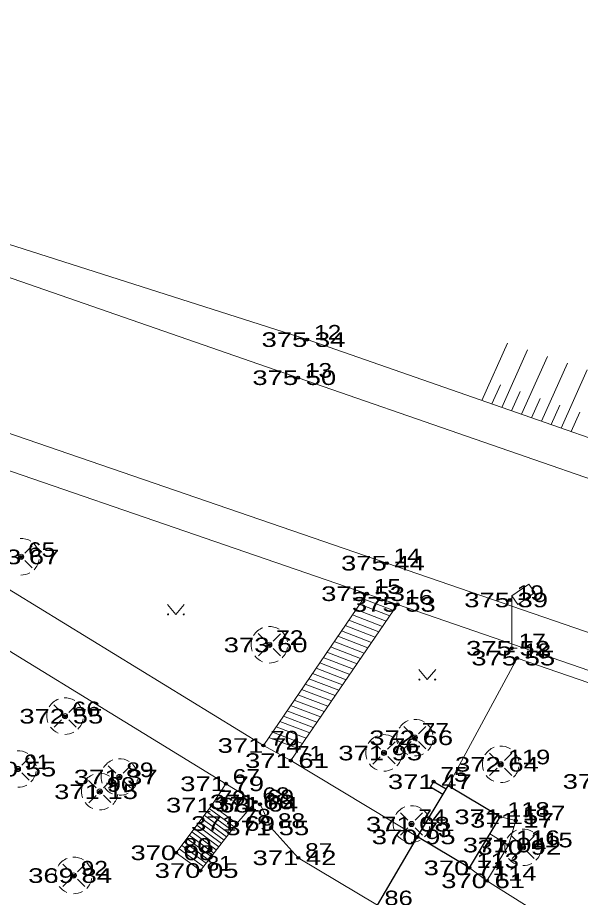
# Model space of a CAD drawing. Extents: x -789669 to -789458, y -977587 to -977420.
# Drawn here: x -789622.43 to -789595.52, y -977462.39 to -977420.32 of the extents above; entities that cross this region are included whole.
import ezdxf
from ezdxf.enums import TextEntityAlignment as Align

# ---------------------------------------------------------------- set-up
doc = ezdxf.new("R2010")
doc.units = 0
doc.header["$LTSCALE"] = 0.28
doc.header["$PDMODE"] = 32
doc.header["$PDSIZE"] = 0.14
for name, color, linetype, lineweight in [('1', 7, 'Continuous', 13), ('2', 7, 'Continuous', 13), ('3', 7, 'Continuous', 13), ('33', 7, 'Continuous', 13), ('4', 7, 'Continuous', 13), ('9', 7, 'Continuous', 25)]:
    doc.layers.add(name, color=color, linetype=linetype, lineweight=lineweight)
for name, color, linetype in [('57', 7, 'Continuous'), ('58', 7, 'Continuous'), ('59', 7, 'Continuous')]:
    doc.layers.add(name, color=color, linetype=linetype)

msp = doc.modelspace()

# ---------------------------------------------------------------- linework, layer by layer
at = {"layer": '1'}
for p, q in [((-789605.73, -977447.87), (-789610.68, -977455.13)), ((-789605.73, -977447.87), (-789604.26, -977448.38)), ((-789609.37, -977455.85), (-789604.26, -977448.38)), ((-789606.076, -977448.377), (-789604.634, -977448.927)), ((-789605.902, -977448.123), (-789604.46, -977448.672)), ((-789606.424, -977448.887), (-789604.983, -977449.436)), ((-789606.25, -977448.633), (-789604.809, -977449.182)), ((-789606.597, -977449.142), (-789605.157, -977449.691)), ((-789606.945, -977449.652), (-789605.505, -977450.2)), ((-789606.771, -977449.397), (-789605.331, -977449.946)), ((-789607.293, -977450.162), (-789605.854, -977450.71)), ((-789607.118, -977449.906), (-789605.679, -977450.455)), ((-789607.466, -977450.416), (-789606.028, -977450.964)), ((-789607.814, -977450.926), (-789606.376, -977451.474)), ((-789607.64, -977450.671), (-789606.202, -977451.219)), ((-789607.987, -977451.18), (-789606.55, -977451.728)), ((-789608.334, -977451.69), (-789606.898, -977452.236)), ((-789608.161, -977451.435), (-789606.724, -977451.982)), ((-789608.682, -977452.2), (-789607.247, -977452.746)), ((-789608.508, -977451.945), (-789607.072, -977452.491)), ((-789608.856, -977452.454), (-789607.421, -977453)), ((-789609.203, -977452.964), (-789607.769, -977453.51)), ((-789609.03, -977452.71), (-789607.595, -977453.256)), ((-789609.551, -977453.474), (-789608.118, -977454.02)), ((-789609.377, -977453.219), (-789607.944, -977453.765)), ((-789609.725, -977453.729), (-789608.292, -977454.274)), ((-789610.072, -977454.238), (-789608.64, -977454.783)), ((-789609.898, -977453.984), (-789608.466, -977454.529)), ((-789610.419, -977454.748), (-789608.989, -977455.292)), ((-789610.246, -977454.493), (-789608.814, -977455.038)), ((-789610.68, -977455.13), (-789609.37, -977455.85)), ((-789613.15, -977457.98), (-789612.47, -977456.96)), ((-789613.269, -977458.14), (-789612.072, -977459.018)), ((-789613.15, -977457.98), (-789611.95, -977458.86)), ((-789611.95, -977458.86), (-789611.05, -977457.83)), ((-789613.509, -977458.461), (-789612.317, -977459.335)), ((-789613.389, -977458.301), (-789612.195, -977459.177)), ((-789613.868, -977458.942), (-789612.685, -977459.81)), ((-789613.747, -977458.781), (-789612.562, -977459.651)), ((-789613.628, -977458.621), (-789612.439, -977459.493)), ((-789614.106, -977459.262), (-789612.929, -977460.126)), ((-789613.987, -977459.102), (-789612.807, -977459.968)), ((-789599.85, -977459.354), (-789598.96, -977459.89)), ((-789614.465, -977459.744), (-789613.296, -977460.601)), ((-789614.346, -977459.584), (-789613.174, -977460.443)), ((-789614.226, -977459.423), (-789613.052, -977460.284)), ((-789614.704, -977460.064), (-789613.541, -977460.917)), ((-789614.584, -977459.904), (-789613.418, -977460.759))]:
    msp.add_line(p, q, dxfattribs=at)
for points in [[(-789652.33, -977422.61), (-789627.98, -977430.97), (-789609.02, -977437.54), (-789583.63, -977446.35), (-789563.97, -977453.25), (-789542.04, -977460.63), (-789524.21, -977466.84), (-789507.23, -977472.64), (-789487.17, -977479.36)], [(-789509.64, -977479.12), (-789526.32, -977473.4), (-789544.78, -977467.07), (-789566.2, -977459.68), (-789586.28, -977452.77), (-789604.78, -977446.41), (-789630.61, -977437.53), (-789654.9, -977429.37)], [(-789638.94, -977437.9), (-789640, -977437), (-789640.69, -977435.9), (-789631.39, -977439.05), (-789605.73, -977447.87), (-789604.26, -977448.38)], [(-789638.94, -977437.9), (-789627.42, -977444.87), (-789610.68, -977455.13), (-789609.37, -977455.85), (-789603.31, -977459.5)], [(-789605.23, -977462.77), (-789609.01, -977460.5), (-789610.31, -977459.07), (-789610.84, -977457.94), (-789611.05, -977457.83), (-789612.47, -977456.96), (-789628.38, -977447.2), (-789642.41, -977438.73)], [(-789604.26, -977448.38), (-789586.79, -977454.41), (-789566.59, -977461.37), (-789545.35, -977468.71), (-789526.33, -977475.15), (-789510.21, -977480.66), (-789489.34, -977487.73), (-789463.94, -977496.44)], [(-789614.85, -977460.26), (-789613.15, -977457.98), (-789611.95, -977458.86)], [(-789599.99, -977461.6), (-789598.96, -977459.89), (-789598.61, -977458.71), (-789599.36, -977458.54)], [(-789614.85, -977460.26), (-789613.69, -977461.11), (-789611.95, -977458.86)], [(-789600.83, -977460.98), (-789599.99, -977461.6), (-789595.27, -977464.56), (-789592.61, -977466.2), (-789587.43, -977468.12), (-789579.25, -977471.12)]]:
    msp.add_lwpolyline(points, dxfattribs=at)
at = {"layer": '2'}
for p, q in [((-789599.004, -977435.891), (-789600.232, -977438.628)), ((-789599.284, -977438.958), (-789598.051, -977436.209)), ((-789598.336, -977439.288), (-789597.097, -977436.527)), ((-789597.388, -977439.617), (-789596.144, -977436.845)), ((-789596.44, -977439.947), (-789595.191, -977437.164)), ((-789599.758, -977438.793), (-789599.348, -977437.879)), ((-789598.81, -977439.123), (-789598.398, -977438.205)), ((-789597.862, -977439.453), (-789597.448, -977438.531)), ((-789596.914, -977439.782), (-789596.499, -977438.857)), ((-789595.966, -977440.112), (-789595.549, -977439.183))]:
    msp.add_line(p, q, dxfattribs=at)
msp.add_lwpolyline([(-789651.99, -977420.32), (-789627.42, -977429.7), (-789608.58, -977435.72), (-789582.71, -977444.73), (-789563.37, -977451.38), (-789541.29, -977458.45), (-789523.64, -977464.38), (-789506.63, -977471.11), (-789487.17, -977479.36)], dxfattribs=at)
at = {"layer": '3', "lineweight": 25}
msp.add_line((-789605.23, -977462.77), (-789603.31, -977459.5), dxfattribs=at)
at = {"layer": '3'}
msp.add_lwpolyline([(-789601.84, -977457.06), (-789598.55, -977450.95), (-789566.5, -977461.99), (-789545.47, -977469.2), (-789526.54, -977475.63), (-789520.95, -977477.5)], dxfattribs=at)
at = {"layer": '33'}
for p, q in [((-789598.8, -977447.98), (-789598.8, -977450.48)), ((-789599.05, -977450.48), (-789598.55, -977450.48))]:
    msp.add_line(p, q, dxfattribs=at)
msp.add_lwpolyline([(-789598.8, -977447.98), (-789597.98, -977447.407), (-789597.694, -977447.817), (-789598.514, -977448.39)], close=True, dxfattribs=at)
at = {"layer": '4'}
for p, q in [((-789621.734, -977445.574), (-789622.087, -977445.927)), ((-789622.26, -977446.11), (-789622.26, -977446.098)), ((-789622.086, -977446.281), (-789621.734, -977446.631)), ((-789610.924, -977449.776), (-789610.567, -977450.132)), ((-789609.864, -977449.784), (-789610.217, -977450.137)), ((-789610.92, -977450.847), (-789610.568, -977450.496)), ((-789610.39, -977450.32), (-789610.39, -977450.308)), ((-789610.216, -977450.491), (-789609.864, -977450.841)), ((-789620.694, -977453.186), (-789620.337, -977453.542)), ((-789619.634, -977453.194), (-789619.987, -977453.547)), ((-789620.69, -977454.257), (-789620.338, -977453.906)), ((-789620.16, -977453.73), (-789620.16, -977453.718)), ((-789619.986, -977453.901), (-789619.634, -977454.251)), ((-789603.964, -977454.216), (-789603.607, -977454.572)), ((-789602.904, -977454.224), (-789603.257, -977454.577)), ((-789603.43, -977454.76), (-789603.43, -977454.748)), ((-789605.444, -977454.946), (-789605.087, -977455.302)), ((-789604.384, -977454.954), (-789604.737, -977455.307)), ((-789603.96, -977455.287), (-789603.608, -977454.936)), ((-789603.256, -977454.931), (-789602.904, -977455.281)), ((-789604.91, -977455.49), (-789604.91, -977455.478)), ((-789599.864, -977455.492), (-789599.507, -977455.848)), ((-789598.804, -977455.5), (-789599.157, -977455.853)), ((-789621.884, -977455.724), (-789622.237, -977456.077)), ((-789605.44, -977456.017), (-789605.088, -977455.666)), ((-789604.736, -977455.661), (-789604.384, -977456.011)), ((-789599.33, -977456.036), (-789599.33, -977456.024)), ((-789622.41, -977456.26), (-789622.41, -977456.248)), ((-789622.236, -977456.431), (-789621.884, -977456.781)), ((-789618.094, -977456.096), (-789617.737, -977456.452)), ((-789617.034, -977456.104), (-789617.387, -977456.457)), ((-789599.86, -977456.563), (-789599.508, -977456.212)), ((-789599.156, -977456.207), (-789598.804, -977456.557)), ((-789619.034, -977456.796), (-789618.677, -977457.152)), ((-789617.974, -977456.804), (-789618.327, -977457.157)), ((-789618.09, -977457.167), (-789617.738, -977456.816)), ((-789617.56, -977456.64), (-789617.56, -977456.628)), ((-789617.386, -977456.811), (-789617.034, -977457.161)), ((-789619.03, -977457.867), (-789618.678, -977457.516)), ((-789618.5, -977457.34), (-789618.5, -977457.328)), ((-789618.326, -977457.511), (-789617.974, -977457.861)), ((-789604.124, -977458.346), (-789603.767, -977458.702)), ((-789603.064, -977458.354), (-789603.417, -977458.707)), ((-789603.59, -977458.89), (-789603.59, -977458.878)), ((-789604.12, -977459.417), (-789603.768, -977459.066)), ((-789603.416, -977459.061), (-789603.064, -977459.411)), ((-789598.794, -977459.462), (-789598.437, -977459.818)), ((-789597.734, -977459.47), (-789598.087, -977459.823)), ((-789598.79, -977460.533), (-789598.438, -977460.182)), ((-789598.26, -977460.006), (-789598.26, -977459.994)), ((-789598.086, -977460.177), (-789597.734, -977460.527)), ((-789620.274, -977460.806), (-789619.917, -977461.162)), ((-789619.214, -977460.814), (-789619.567, -977461.167)), ((-789619.74, -977461.35), (-789619.74, -977461.338)), ((-789619.566, -977461.521), (-789619.214, -977461.871)), ((-789620.27, -977461.877), (-789619.918, -977461.526))]:
    msp.add_line(p, q, dxfattribs=at)
for points in [[(-789615.264, -977448.381), (-789614.862, -977448.86), (-789614.46, -977448.381)], [(-789615.236, -977448.837), (-789615.222, -977448.845), (-789615.217, -977448.86), (-789615.223, -977448.873), (-789615.236, -977448.881), (-789615.252, -977448.873), (-789615.258, -977448.86), (-789615.254, -977448.846), (-789615.243, -977448.84), (-789615.228, -977448.846), (-789615.223, -977448.86), (-789615.226, -977448.87), (-789615.236, -977448.875), (-789615.247, -977448.87), (-789615.253, -977448.859), (-789615.248, -977448.849), (-789615.243, -977448.846), (-789615.232, -977448.85), (-789615.227, -977448.86), (-789615.233, -977448.867), (-789615.241, -977448.865), (-789615.246, -977448.857), (-789615.241, -977448.852), (-789615.233, -977448.856), (-789615.236, -977448.86)], [(-789614.486, -977448.838), (-789614.472, -977448.846), (-789614.467, -977448.861), (-789614.473, -977448.874), (-789614.486, -977448.882), (-789614.502, -977448.874), (-789614.508, -977448.861), (-789614.504, -977448.847), (-789614.493, -977448.841), (-789614.478, -977448.847), (-789614.473, -977448.861), (-789614.476, -977448.871), (-789614.486, -977448.876), (-789614.497, -977448.871), (-789614.503, -977448.86), (-789614.498, -977448.85), (-789614.493, -977448.847), (-789614.482, -977448.851), (-789614.477, -977448.861), (-789614.483, -977448.868), (-789614.491, -977448.866), (-789614.496, -977448.858), (-789614.491, -977448.853), (-789614.483, -977448.857), (-789614.486, -977448.861)], [(-789603.243, -977451.5), (-789602.841, -977451.979), (-789602.439, -977451.5)], [(-789603.215, -977451.956), (-789603.201, -977451.964), (-789603.196, -977451.979), (-789603.202, -977451.992), (-789603.215, -977452), (-789603.231, -977451.992), (-789603.237, -977451.979), (-789603.233, -977451.965), (-789603.222, -977451.959), (-789603.207, -977451.965), (-789603.202, -977451.979), (-789603.205, -977451.989), (-789603.215, -977451.994), (-789603.226, -977451.989), (-789603.232, -977451.978), (-789603.227, -977451.968), (-789603.222, -977451.965), (-789603.211, -977451.969), (-789603.206, -977451.979), (-789603.212, -977451.986), (-789603.22, -977451.984), (-789603.225, -977451.976), (-789603.22, -977451.971), (-789603.212, -977451.975), (-789603.215, -977451.979)], [(-789602.465, -977451.957), (-789602.451, -977451.965), (-789602.446, -977451.98), (-789602.452, -977451.993), (-789602.465, -977452.001), (-789602.481, -977451.993), (-789602.487, -977451.98), (-789602.483, -977451.966), (-789602.472, -977451.96), (-789602.457, -977451.966), (-789602.452, -977451.98), (-789602.455, -977451.99), (-789602.465, -977451.995), (-789602.476, -977451.99), (-789602.482, -977451.979), (-789602.477, -977451.969), (-789602.472, -977451.966), (-789602.461, -977451.97), (-789602.456, -977451.98), (-789602.462, -977451.987), (-789602.47, -977451.985), (-789602.475, -977451.977), (-789602.47, -977451.972), (-789602.462, -977451.976), (-789602.465, -977451.98)]]:
    msp.add_lwpolyline(points, dxfattribs=at)
for centre, radius in [((-789622.2639, -977446.1034), 0.125), ((-789615.237, -977448.86), 0.025), ((-789614.487, -977448.86), 0.025), ((-789610.3939, -977450.3134), 0.125), ((-789603.216, -977451.979), 0.025), ((-789602.466, -977451.979), 0.025), ((-789620.1639, -977453.7234), 0.125), ((-789603.4339, -977454.7534), 0.125), ((-789604.9139, -977455.4834), 0.125), ((-789599.3339, -977456.0294), 0.125), ((-789622.4139, -977456.2534), 0.125), ((-789617.5639, -977456.6334), 0.125), ((-789618.5039, -977457.3334), 0.125), ((-789603.5939, -977458.8834), 0.125), ((-789598.2639, -977459.9994), 0.125), ((-789619.7439, -977461.3434), 0.125)]:
    msp.add_circle(centre, radius, dxfattribs=at)
for centre, start, end in [((-789622.2639, -977446.1034), 57.94289, 92.85253), ((-789622.2639, -977446.1034), 9.68453, 44.47714), ((-789622.2639, -977446.1034), 315.09105, 351.67435), ((-789622.2639, -977446.1034), 269.18965, 298.56841), ((-789610.3939, -977450.3134), 111.04924, 149.34666), ((-789610.3939, -977450.3134), 57.94289, 92.85253), ((-789610.3939, -977450.3134), 9.68453, 44.47714), ((-789610.3939, -977450.3134), 166.76695, 200.11735), ((-789610.3939, -977450.3134), 315.09105, 351.67435), ((-789610.3939, -977450.3134), 217.06959, 247.69959), ((-789610.3939, -977450.3134), 269.18965, 298.56841), ((-789620.1639, -977453.7234), 111.04924, 149.34666), ((-789620.1639, -977453.7234), 57.94289, 92.85253), ((-789620.1639, -977453.7234), 166.76695, 200.11735), ((-789620.1639, -977453.7234), 9.68453, 44.47714), ((-789620.1639, -977453.7234), 315.09105, 351.67435), ((-789603.4339, -977454.7534), 111.04924, 149.34666), ((-789603.4339, -977454.7534), 57.94289, 92.85253), ((-789620.1639, -977453.7234), 217.06959, 247.69959), ((-789603.4339, -977454.7534), 9.68453, 44.47714), ((-789620.1639, -977453.7234), 269.18965, 298.56841), ((-789604.9139, -977455.4834), 111.04924, 149.34666), ((-789604.9139, -977455.4834), 57.94289, 92.85253), ((-789603.4339, -977454.7534), 166.76695, 200.11735), ((-789604.9139, -977455.4834), 9.68453, 44.47714), ((-789603.4339, -977454.7534), 315.09105, 351.67435), ((-789599.3339, -977456.0294), 57.94289, 92.85253), ((-789622.4139, -977456.2534), 57.94289, 92.85253), ((-789604.9139, -977455.4834), 166.76695, 200.11735), ((-789604.9139, -977455.4834), 315.09105, 351.67435), ((-789603.4339, -977454.7534), 217.06959, 247.69959), ((-789603.4339, -977454.7534), 269.18965, 298.56841), ((-789599.3339, -977456.0294), 111.04924, 149.34666), ((-789599.3339, -977456.0294), 9.68453, 44.47714), ((-789622.4139, -977456.2534), 9.68453, 44.47714), ((-789617.5639, -977456.6334), 111.04924, 149.34666), ((-789617.5639, -977456.6334), 57.94289, 92.85253), ((-789617.5639, -977456.6334), 9.68453, 44.47714), ((-789604.9139, -977455.4834), 217.06959, 247.69959), ((-789599.3339, -977456.0294), 166.76695, 200.11735), ((-789622.4139, -977456.2534), 315.09105, 351.67435), ((-789618.5039, -977457.3334), 57.94289, 92.85253), ((-789617.5639, -977456.6334), 166.76695, 200.11735), ((-789604.9139, -977455.4834), 269.18965, 298.56841), ((-789599.3339, -977456.0294), 315.09105, 351.67435), ((-789618.5039, -977457.3334), 111.04924, 149.34666), ((-789618.5039, -977457.3334), 9.68453, 44.47714), ((-789617.5639, -977456.6334), 315.09105, 351.67435), ((-789599.3339, -977456.0294), 217.06959, 247.69959), ((-789599.3339, -977456.0294), 269.18965, 298.56841), ((-789622.4139, -977456.2534), 269.18965, 298.56841), ((-789618.5039, -977457.3334), 166.76695, 200.11735), ((-789617.5639, -977456.6334), 217.06959, 247.69959), ((-789618.5039, -977457.3334), 315.09105, 351.67435), ((-789617.5639, -977456.6334), 269.18965, 298.56841), ((-789618.5039, -977457.3334), 217.06959, 247.69959), ((-789618.5039, -977457.3334), 269.18965, 298.56841), ((-789603.5939, -977458.8834), 111.04924, 149.34666), ((-789603.5939, -977458.8834), 57.94289, 92.85253), ((-789603.5939, -977458.8834), 9.68453, 44.47714), ((-789603.5939, -977458.8834), 166.76695, 200.11735), ((-789603.5939, -977458.8834), 217.06959, 247.69959), ((-789603.5939, -977458.8834), 315.09105, 351.67435), ((-789598.2639, -977459.9994), 111.04924, 149.34666), ((-789598.2639, -977459.9994), 57.94289, 92.85253), ((-789598.2639, -977459.9994), 9.68453, 44.47714), ((-789603.5939, -977458.8834), 269.18965, 298.56841), ((-789598.2639, -977459.9994), 166.76695, 200.11735), ((-789598.2639, -977459.9994), 315.09105, 351.67435), ((-789619.7439, -977461.3434), 111.04924, 149.34666), ((-789619.7439, -977461.3434), 57.94289, 92.85253), ((-789598.2639, -977459.9994), 217.06959, 247.69959), ((-789619.7439, -977461.3434), 9.68453, 44.47714), ((-789598.2639, -977459.9994), 269.18965, 298.56841), ((-789619.7439, -977461.3434), 166.76695, 200.11735), ((-789619.7439, -977461.3434), 315.09105, 351.67435), ((-789619.7439, -977461.3434), 217.06959, 247.69959), ((-789619.7439, -977461.3434), 269.18965, 298.56841)]:
    msp.add_arc(centre, 0.875, start, end, dxfattribs=at)
at = {"layer": '57'}
for p in [(-789608.58, -977435.72), (-789609.02, -977437.54), (-789622.26, -977446.11), (-789604.78, -977446.41), (-789605.73, -977447.87), (-789604.26, -977448.38), (-789598.89, -977448.17), (-789610.39, -977450.32), (-789598.8, -977450.48), (-789598.55, -977450.95), (-789620.16, -977453.73), (-789603.43, -977454.76), (-789610.68, -977455.13), (-789604.91, -977455.49), (-789609.37, -977455.85), (-789599.33, -977456.03), (-789622.41, -977456.26), (-789617.56, -977456.64), (-789612.47, -977456.96), (-789602.54, -977456.86), (-789618.5, -977457.34), (-789613.15, -977457.98), (-789611.05, -977457.83), (-789610.84, -977457.94), (-789599.36, -977458.54), (-789611.95, -977458.86), (-789603.59, -977458.89), (-789598.61, -977458.71), (-789610.31, -977459.07), (-789603.31, -977459.5), (-789598.96, -977459.89), (-789614.85, -977460.26), (-789598.26, -977460), (-789609.01, -977460.5), (-789613.69, -977461.11), (-789600.83, -977460.98), (-789619.74, -977461.35), (-789599.99, -977461.6)]:
    msp.add_point(p, dxfattribs=at)
at = {"layer": '9'}
for p, q in [((-789602.695, -977457.117), (-789602.54, -977456.86)), ((-789601.938, -977457.223), (-789602.54, -977456.86)), ((-789603.31, -977459.5), (-789601.84, -977457.06)), ((-789602.093, -977457.48), (-789602.695, -977457.117)), ((-789599.36, -977458.54), (-789601.84, -977457.06)), ((-789600.83, -977460.98), (-789599.36, -977458.54)), ((-789600.83, -977460.98), (-789603.31, -977459.5))]:
    msp.add_line(p, q, dxfattribs=at)

# ---------------------------------------------------------------- texts
at = {"layer": '58'}
for s, width, p in [(' 12', 1.25, (-789608.58, -977435.72)), (' 13', 1.25, (-789609.02, -977437.54)), (' 65', 1.25, (-789622.26, -977446.11)), (' 14', 1.25, (-789604.78, -977446.41)), (' 15', 1.25, (-789605.73, -977447.87)), (' 19', 1.25, (-789598.89, -977448.17)), (' 16', 1.3, (-789604.26, -977448.38)), (' 72', 1.25, (-789610.39, -977450.32)), (' 17', 1.25, (-789598.8, -977450.48)), (' 18', 1.25, (-789598.55, -977450.95)), (' 66', 1.3, (-789620.16, -977453.73)), (' 77', 1.25, (-789603.43, -977454.76)), (' 70', 1.3, (-789610.68, -977455.13)), (' 76', 1.3, (-789604.91, -977455.49)), (' 71', 1.15, (-789609.37, -977455.85)), (' 91', 1.15, (-789622.41, -977456.26)), (' 119', 1.3, (-789599.33, -977456.03)), (' 89', 1.25, (-789617.56, -977456.64)), (' 67', 1.25, (-789612.47, -977456.96)), (' 75', 1.25, (-789602.54, -977456.86)), (' 90', 1.3, (-789618.5, -977457.34)), (' 79', 1.25, (-789613.15, -977457.98)), (' 68', 1.25, (-789611.05, -977457.83)), (' 69', 1.25, (-789610.84, -977457.94)), (' 78', 1.25, (-789611.95, -977458.86)), (' 118', 1.3, (-789599.36, -977458.54)), (' 117', 1.3, (-789598.61, -977458.71)), (' 88', 1.25, (-789610.31, -977459.07)), (' 74', 1.25, (-789603.59, -977458.89)), (' 73', 1.25, (-789603.31, -977459.5)), (' 116', 1.35, (-789598.96, -977459.89)), (' 115', 1.3, (-789598.26, -977460)), (' 80', 1.3, (-789614.85, -977460.26)), (' 87', 1.25, (-789609.01, -977460.5)), (' 92', 1.25, (-789619.74, -977461.35)), (' 81', 1.15, (-789613.69, -977461.11)), (' 113', 1.3, (-789600.83, -977460.98)), (' 114', 1.3, (-789599.99, -977461.6)), (' 86', 1.3, (-789605.23, -977462.77))]:
    msp.add_text(s, height=0.7, dxfattribs=dict(at, width=width)).set_placement(p)
at = {"layer": '59', "width": 1.4}
for s, p in [('375 34 ', (-789608.58, -977436.07)), ('375 50 ', (-789609.02, -977437.89)), ('373 67 ', (-789622.26, -977446.46)), ('375 44 ', (-789604.78, -977446.76)), ('375 53 ', (-789605.73, -977448.22)), ('375 53 ', (-789604.26, -977448.73)), ('375 39 ', (-789598.89, -977448.52)), ('373 60 ', (-789610.39, -977450.67)), ('375 52 ', (-789598.8, -977450.83)), ('375 55 ', (-789598.55, -977451.3)), ('372 55 ', (-789620.16, -977454.08)), ('371 74 ', (-789610.68, -977455.48)), ('372 66 ', (-789603.43, -977455.11)), ('371 95 ', (-789604.91, -977455.84)), ('371 61 ', (-789609.37, -977456.2)), ('370 55 ', (-789622.41, -977456.61)), ('372 64 ', (-789599.33, -977456.38)), ('371 37 ', (-789617.56, -977456.99)), ('371 79 ', (-789612.47, -977457.31)), ('371 47 ', (-789602.54, -977457.21)), ('372 99 ', (-789594.18, -977457.2)), ('371 15 ', (-789618.5, -977457.69)), ('371 68 ', (-789613.15, -977458.33)), ('371 66 ', (-789611.05, -977458.18)), ('371 64 ', (-789610.84, -977458.29)), ('371 69 ', (-789611.95, -977459.21)), ('371 08 ', (-789603.59, -977459.24)), ('371 15 ', (-789599.36, -977458.89)), ('371 17 ', (-789598.61, -977459.06)), ('371 55 ', (-789610.31, -977459.42)), ('370 95 ', (-789603.31, -977459.85)), ('371 04 ', (-789598.96, -977460.24)), ('370 92 ', (-789598.26, -977460.35)), ('370 08 ', (-789614.85, -977460.61)), ('371 42 ', (-789609.01, -977460.85)), ('370 71 ', (-789600.83, -977461.33)), ('369 84 ', (-789619.74, -977461.7)), ('370 05 ', (-789613.69, -977461.46)), ('370 61 ', (-789599.99, -977461.95))]:
    msp.add_text(s, height=0.7, dxfattribs=at).set_placement(p, align=Align.CENTER)

doc.saveas('drawing.dxf')
